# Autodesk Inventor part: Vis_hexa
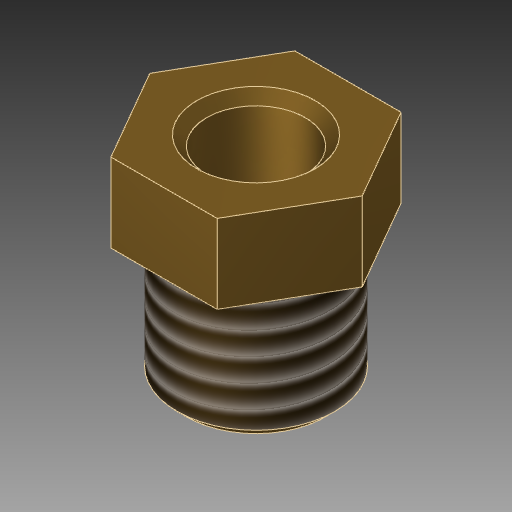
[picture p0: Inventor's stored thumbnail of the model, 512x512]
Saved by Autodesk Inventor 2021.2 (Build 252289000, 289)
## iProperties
Created: 2018-06
Part Number: Vis_hexa
Material: Laiton, jaune doux
Document SubType Name: Modeling
Designer: Fabian Perrée
Density: 8.47 g/cm^3
Appearance: Laiton - Satiné
Author: Fabian Perrée
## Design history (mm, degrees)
sketch "Esquisse1"
  geometry: C1 r 6 at (0, 0); C2 r 3.75 at (0, 0); 1 further point
  constraints: 2 centre point, 2 coincident
  dimensions: "d0" = 12 diameter of C1; "d1" = 7.5 diameter of C2
extrude "Extrusion1" new body sketch "Esquisse1" distance "d2" = 16; taper "d3" = 0 deg
sketch "Esquisse2"
  geometry: L1 (4.041, -7)-(-4.041, -7); L2 (-4.041, -7)-(-8.083, 0); L3 (-8.083, 0)-(-4.041, 7); L4 (-4.041, 7)-(4.041, 7); L5 (4.041, 7)-(8.083, 0); L6 (8.083, 0)-(4.041, -7); C1 r 3.75 at (0, 0) reference; C2 r 6 at (0, 0) reference; 1 further point
  constraints: 12 end point, 1 coincident, 1 horizontal, 13 other
  dimensions: "d4" = 14 distance between parallel lines of L4 L1
extrude "Extrusion2" join sketch "Esquisse2" distance "d5" = 6; taper "d6" = 0 deg
chamfer "Chanfrein1" distance "d7" = 0.75; stored, may be unused: second distance "d8" = 2, angle "d9" = 45 deg
feature "Filetage1" dims "d10" = 10, "d11" = 0
node "Solide1"
